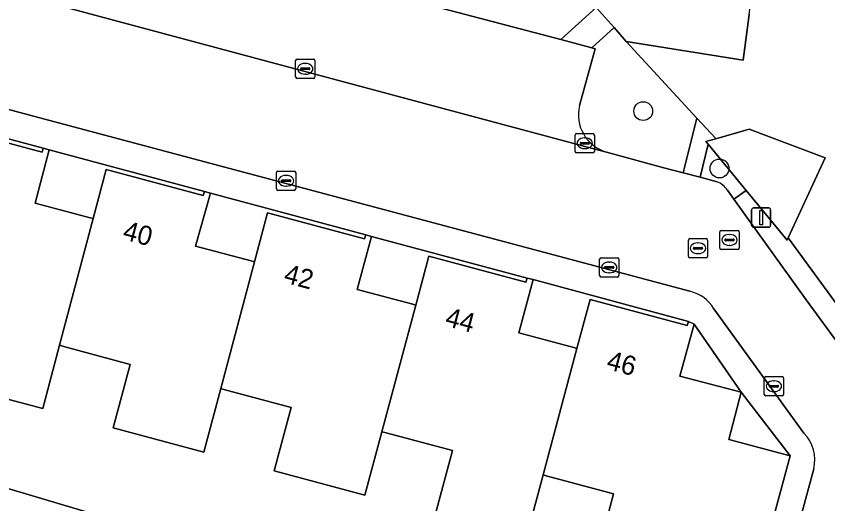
# Model space of a CAD drawing. Extents: x 162989 to 165008, y 383432 to 384338.
# Drawn here: x 163614.99 to 163657.21, y 383922.58 to 383947.94 of the extents above; entities that cross this region are included whole.
import ezdxf

# ---------------------------------------------------------------- set-up
doc = ezdxf.new("R2010")
doc.units = 0
for name, color, linetype in [('IMGEO_Boom', 7, 'Continuous'), ('IMGEO_Erf', 7, 'Continuous'), ('IMGEO_Geluidsscherm', 7, 'Continuous'), ('IMGEO_Grasland_overig', 7, 'Continuous'), ('IMGEO_Groenvoorziening', 7, 'Continuous'), ('IMGEO_Kolk', 7, 'Continuous'), ('IMGEO_Lichtmast', 7, 'Continuous'), ('IMGEO_Pand', 7, 'Continuous'), ('IMGEO_Pand_nummerreeks', 7, 'Continuous'), ('IMGEO_Parkeervlak_open', 7, 'Continuous'), ('IMGEO_Rijbaan_lokaal_open', 7, 'Continuous'), ('IMGEO_Rioolput', 7, 'Continuous'), ('IMGEO_Voetpad_open', 7, 'Continuous')]:
    doc.layers.add(name, color=color, linetype=linetype)

msp = doc.modelspace()

# ---------------------------------------------------------------- linework, layer by layer
at = {"layer": 'IMGEO_Boom'}
for centre in [(163647.609, 383943.003), (163651.576, 383940.019)]:
    msp.add_circle(centre, 0.489, dxfattribs=at)
at = {"layer": 'IMGEO_Erf'}
for points in [[(163653.122, 383948.03), (163652.805, 383945.653), (163646.728, 383946.625), (163650.396, 383942.642), (163651.363, 383941.592), (163651.385, 383941.562), (163653.125, 383942.063), (163657.071, 383940.58), (163655.156, 383936.406), (163662.9, 383925.817)], [(163564.646, 383935.431), (163579.692, 383931.881), (163589.465, 383929.727), (163599.072, 383927.517), (163605.168, 383926.118), (163613.02, 383923.823), (163634.587, 383917.404), (163655.721, 383911.082), (163672.29, 383906.041)], [(163673.981, 383906.039), (163651.937, 383912.722), (163653.247, 383917.636), (163645.188, 383919.799), (163646.071, 383923.092), (163642.556, 383924.039), (163642.4, 383924.081), (163641.519, 383920.786), (163636.802, 383922.049), (163637.684, 383925.343), (163634.164, 383926.279), (163634.006, 383926.321), (163633.124, 383923.028), (163628.41, 383924.295), (163629.295, 383927.588), (163625.786, 383928.523), (163625.624, 383928.567), (163624.746, 383925.272), (163620.03, 383926.538), (163620.914, 383929.831), (163617.398, 383930.782), (163617.242, 383930.824), (163616.366, 383927.527), (163611.629, 383928.789)]]:
    msp.add_lwpolyline(points, dxfattribs=at)
for points in [[(163616.395, 383941.068), (163610.107, 383942.758), (163608.296, 383943.245), (163607.535, 383940.488), (163610.436, 383939.707), (163610.597, 383939.663), (163611.276, 383942.214), (163616.331, 383940.858)], [(163624.788, 383938.825), (163616.704, 383940.986), (163615.972, 383938.221), (163618.835, 383937.451), (163618.992, 383937.409), (163619.67, 383939.96), (163624.72, 383938.612)], [(163633.173, 383936.569), (163625.089, 383938.741), (163624.318, 383935.986), (163627.217, 383935.207), (163627.378, 383935.164), (163628.057, 383937.715), (163633.113, 383936.354)], [(163641.567, 383934.32), (163633.48, 383936.485), (163632.721, 383933.728), (163635.615, 383932.954), (163635.771, 383932.912), (163636.454, 383935.462), (163641.499, 383934.108)], [(163649.958, 383932.065), (163641.878, 383934.236), (163641.13, 383931.476), (163644.006, 383930.701), (163644.16, 383930.659), (163644.843, 383933.211), (163649.9, 383931.859)], [(163650.253, 383931.917), (163649.521, 383929.222), (163652.71, 383928.376)], [(163652.71, 383928.376), (163652.069, 383925.927), (163655.256, 383925.07)]]:
    msp.add_lwpolyline(points, close=True, dxfattribs=at)
at = {"layer": 'IMGEO_Geluidsscherm'}
msp.add_lwpolyline([(163555.79, 383937.222), (163564.646, 383935.431), (163579.692, 383931.881), (163589.465, 383929.727), (163599.072, 383927.517), (163605.168, 383926.118), (163613.02, 383923.823), (163634.587, 383917.404), (163655.721, 383911.082), (163672.29, 383906.041), (163680.003, 383903.652), (163680.457, 383903.531)], dxfattribs=at)
at = {"layer": 'IMGEO_Grasland_overig'}
msp.add_lwpolyline([(163569.036, 383926.529), (163593.547, 383921.194), (163594.114, 383923.205), (163597.332, 383922.493), (163596.824, 383920.182), (163602.361, 383919.022), (163634.665, 383911.508), (163670.387, 383902.701), (163679.08, 383900.453), (163680.003, 383903.652), (163672.29, 383906.041), (163655.721, 383911.082), (163634.587, 383917.404), (163613.02, 383923.823), (163605.168, 383926.118), (163599.072, 383927.517), (163589.465, 383929.727), (163579.692, 383931.881), (163564.646, 383935.431)], dxfattribs=at)
at = {"layer": 'IMGEO_Groenvoorziening'}
for points in [[(163599.35, 383960.383), (163598.199, 383961.094), (163597.764, 383962.949), (163596.978, 383962.778), (163597.581, 383959.99), (163597.843, 383958.853), (163614.246, 383954.444), (163635.514, 383948.776), (163643.317, 383946.719), (163645.161, 383948.398)], [(163650.396, 383942.642), (163646.728, 383946.625), (163646.09, 383947.347), (163644.933, 383946.293), (163645.105, 383946.248), (163644.299, 383943.287)], [(163645.699, 383940.867), (163648.69, 383940.057), (163649.686, 383939.794), (163650.396, 383942.642)], [(163650.987, 383941.275), (163650.575, 383939.559), (163651.448, 383939.329)], [(163651.994, 383938.891), (163652.317, 383938.42), (163652.965, 383938.873), (163650.987, 383941.275)]]:
    msp.add_lwpolyline(points, dxfattribs=at)
for centre, radius, start, end in [((163646.258, 383942.805), 2.017, 166.1857, 253.9141), ((163650.962, 383938.164), 1.262, 35.1609, 67.3661)]:
    msp.add_arc(centre, radius, start, end, dxfattribs=at)
at = {"layer": 'IMGEO_Kolk'}
for p, q in [((163629.525, 383944.776), (163629.525, 383945.628)), ((163629.6, 383945.702), (163630.452, 383945.702)), ((163630.013, 383945.482), (163630.038, 383945.482)), ((163630.526, 383945.628), (163630.526, 383944.776)), ((163629.784, 383945.196), (163629.784, 383945.208)), ((163630.222, 383945.159), (163629.824, 383945.159)), ((163629.827, 383945.245), (163630.225, 383945.245)), ((163630.036, 383944.922), (163630.011, 383944.922)), ((163630.268, 383945.208), (163630.268, 383945.196)), ((163630.452, 383944.702), (163629.6, 383944.702)), ((163644.066, 383940.906), (163644.066, 383941.758)), ((163644.141, 383941.832), (163644.993, 383941.832)), ((163644.554, 383941.612), (163644.579, 383941.612)), ((163645.067, 383941.758), (163645.067, 383940.906)), ((163644.325, 383941.326), (163644.325, 383941.338)), ((163644.763, 383941.289), (163644.365, 383941.289)), ((163644.368, 383941.375), (163644.766, 383941.375)), ((163644.809, 383941.338), (163644.809, 383941.326)), ((163644.993, 383940.832), (163644.141, 383940.832)), ((163644.577, 383941.052), (163644.552, 383941.052)), ((163628.601, 383939.879), (163629.453, 383939.879)), ((163628.526, 383938.953), (163628.526, 383939.805)), ((163628.828, 383939.422), (163629.226, 383939.422)), ((163629.014, 383939.659), (163629.039, 383939.659)), ((163629.527, 383939.805), (163629.527, 383938.953)), ((163628.785, 383939.373), (163628.785, 383939.385)), ((163629.223, 383939.336), (163628.825, 383939.336)), ((163629.037, 383939.099), (163629.012, 383939.099)), ((163629.269, 383939.385), (163629.269, 383939.373)), ((163629.453, 383938.879), (163628.601, 383938.879)), ((163645.339, 383934.447), (163645.339, 383935.299)), ((163645.414, 383935.373), (163646.266, 383935.373)), ((163646.34, 383935.299), (163646.34, 383934.447)), ((163645.598, 383934.867), (163645.598, 383934.879)), ((163646.036, 383934.83), (163645.638, 383934.83)), ((163645.641, 383934.916), (163646.039, 383934.916)), ((163645.827, 383935.153), (163645.852, 383935.153)), ((163646.082, 383934.879), (163646.082, 383934.867)), ((163646.266, 383934.373), (163645.414, 383934.373)), ((163645.85, 383934.593), (163645.825, 383934.593)), ((163653.908, 383928.268), (163653.908, 383929.12)), ((163653.983, 383929.194), (163654.835, 383929.194)), ((163654.396, 383928.974), (163654.421, 383928.974)), ((163654.909, 383929.12), (163654.909, 383928.268)), ((163654.167, 383928.688), (163654.167, 383928.7)), ((163654.605, 383928.651), (163654.207, 383928.651)), ((163654.21, 383928.737), (163654.608, 383928.737)), ((163654.651, 383928.7), (163654.651, 383928.688)), ((163654.835, 383928.194), (163653.983, 383928.194)), ((163654.419, 383928.414), (163654.394, 383928.414))]:
    msp.add_line(p, q, dxfattribs=at)
for points in [[(163629.525, 383944.776), (163629.525, 383945.628)], [(163629.6, 383945.702), (163630.452, 383945.702)], [(163630.526, 383945.628), (163630.526, 383944.776)], [(163630.452, 383944.702), (163629.6, 383944.702)], [(163644.066, 383940.906), (163644.066, 383941.758)], [(163644.141, 383941.832), (163644.993, 383941.832)], [(163645.067, 383941.758), (163645.067, 383940.906)], [(163644.993, 383940.832), (163644.141, 383940.832)], [(163628.601, 383939.879), (163629.453, 383939.879)], [(163628.526, 383938.953), (163628.526, 383939.805)], [(163629.527, 383939.805), (163629.527, 383938.953)], [(163629.453, 383938.879), (163628.601, 383938.879)], [(163645.339, 383934.447), (163645.339, 383935.299)], [(163645.414, 383935.373), (163646.266, 383935.373)], [(163646.34, 383935.299), (163646.34, 383934.447)], [(163646.266, 383934.373), (163645.414, 383934.373)], [(163653.908, 383928.268), (163653.908, 383929.12)], [(163653.983, 383929.194), (163654.835, 383929.194)], [(163654.909, 383929.12), (163654.909, 383928.268)], [(163654.835, 383928.194), (163653.983, 383928.194)]]:
    msp.add_lwpolyline(points, dxfattribs=at)
for centre, radius, start, end in [((163629.602, 383945.626), 0.0765, 91.552, 178.448), ((163629.602, 383945.626), 0.0765, 91.552, 178.448), ((163630.45, 383945.626), 0.0765, 1.552, 88.448), ((163630.45, 383945.626), 0.0765, 1.552, 88.448), ((163629.824, 383945.205), 0.0403, 85.8775, 175.7526), ((163629.821, 383945.195), 0.0366, 178.938, 274.7102), ((163630.225, 383945.202), 0.043, 264.8664, 352.4533), ((163630.229, 383945.207), 0.0386, 1.7309, 96.639), ((163629.602, 383944.778), 0.0765, 181.552, 268.448), ((163629.602, 383944.778), 0.0765, 181.552, 268.448), ((163630.45, 383944.778), 0.0765, 271.552, 358.448), ((163630.45, 383944.778), 0.0765, 271.552, 358.448), ((163644.143, 383941.756), 0.0765, 91.552, 178.448), ((163644.143, 383941.756), 0.0765, 91.552, 178.448), ((163644.991, 383941.756), 0.0765, 1.552, 88.448), ((163644.991, 383941.756), 0.0765, 1.552, 88.448), ((163644.365, 383941.335), 0.0403, 85.8775, 175.7526), ((163644.362, 383941.325), 0.0366, 178.938, 274.7102), ((163644.766, 383941.332), 0.043, 264.8664, 352.4533), ((163644.77, 383941.337), 0.0386, 1.7309, 96.639), ((163644.143, 383940.908), 0.0765, 181.552, 268.448), ((163644.143, 383940.908), 0.0765, 181.552, 268.448), ((163644.991, 383940.908), 0.0765, 271.552, 358.448), ((163644.991, 383940.908), 0.0765, 271.552, 358.448), ((163628.603, 383939.803), 0.0765, 91.552, 178.448), ((163628.603, 383939.803), 0.0765, 91.552, 178.448), ((163629.451, 383939.803), 0.0765, 1.552, 88.448), ((163629.451, 383939.803), 0.0765, 1.552, 88.448), ((163628.825, 383939.382), 0.0403, 85.8775, 175.7526), ((163629.23, 383939.384), 0.0386, 1.7309, 96.639), ((163628.822, 383939.372), 0.0366, 178.938, 274.7102), ((163629.226, 383939.379), 0.043, 264.8664, 352.4533), ((163628.603, 383938.955), 0.0765, 181.552, 268.448), ((163628.603, 383938.955), 0.0765, 181.552, 268.448), ((163629.451, 383938.955), 0.0765, 271.552, 358.448), ((163629.451, 383938.955), 0.0765, 271.552, 358.448), ((163645.416, 383935.297), 0.0765, 91.552, 178.448), ((163645.416, 383935.297), 0.0765, 91.552, 178.448), ((163646.264, 383935.297), 0.0765, 1.552, 88.448), ((163646.264, 383935.297), 0.0765, 1.552, 88.448), ((163645.638, 383934.876), 0.0403, 85.8775, 175.7526), ((163645.635, 383934.866), 0.0366, 178.938, 274.7102), ((163646.039, 383934.873), 0.043, 264.8664, 352.4533), ((163646.043, 383934.878), 0.0386, 1.7309, 96.639), ((163645.416, 383934.449), 0.0765, 181.552, 268.448), ((163645.416, 383934.449), 0.0765, 181.552, 268.448), ((163646.264, 383934.449), 0.0765, 271.552, 358.448), ((163646.264, 383934.449), 0.0765, 271.552, 358.448), ((163653.985, 383929.118), 0.0765, 91.552, 178.448), ((163653.985, 383929.118), 0.0765, 91.552, 178.448), ((163654.833, 383929.118), 0.0765, 1.552, 88.448), ((163654.833, 383929.118), 0.0765, 1.552, 88.448), ((163654.207, 383928.697), 0.0403, 85.8775, 175.7526), ((163654.204, 383928.687), 0.0366, 178.938, 274.7102), ((163654.608, 383928.694), 0.043, 264.8664, 352.4533), ((163654.612, 383928.699), 0.0386, 1.7309, 96.639), ((163653.985, 383928.27), 0.0765, 181.552, 268.448), ((163653.985, 383928.27), 0.0765, 181.552, 268.448), ((163654.833, 383928.27), 0.0765, 271.552, 358.448), ((163654.833, 383928.27), 0.0765, 271.552, 358.448)]:
    msp.add_arc(centre, radius, start, end, dxfattribs=at)
for centre, major_axis, ratio, start_param, end_param in [((163630.012, 383945.202), (-0.387, 0.002), 0.722429, 4.712389, 7.853982), ((163630.037, 383945.202), (-0.39, 0.002), 0.717154, 1.570796, 4.712389), ((163644.553, 383941.332), (-0.387, 0.002), 0.722429, 4.712389, 7.853982), ((163644.578, 383941.332), (-0.39, 0.002), 0.717154, 1.570796, 4.712389), ((163629.013, 383939.379), (-0.387, 0.002), 0.722429, 4.712389, 7.853982), ((163629.038, 383939.379), (-0.39, 0.002), 0.717154, 1.570796, 4.712389), ((163645.826, 383934.873), (-0.387, 0.002), 0.722429, 4.712389, 7.853982), ((163645.851, 383934.873), (-0.39, 0.002), 0.717154, 1.570796, 4.712389), ((163654.395, 383928.694), (-0.387, 0.002), 0.722429, 4.712389, 7.853982), ((163654.42, 383928.694), (-0.39, 0.002), 0.717154, 1.570796, 4.712389)]:
    msp.add_ellipse(centre, major_axis=major_axis, ratio=ratio, start_param=start_param, end_param=end_param, dxfattribs=at)
at = {"layer": 'IMGEO_Lichtmast'}
for p, q in [((163653.248, 383937.064), (163653.248, 383937.864)), ((163653.248, 383937.864), (163653.248, 383937.064)), ((163653.348, 383937.964), (163654.138, 383937.964)), ((163654.138, 383937.964), (163653.348, 383937.964)), ((163654.238, 383937.864), (163654.238, 383937.064)), ((163654.238, 383937.064), (163654.238, 383937.864)), ((163654.138, 383936.964), (163653.348, 383936.964)), ((163653.348, 383936.964), (163654.138, 383936.964))]:
    msp.add_line(p, q, dxfattribs=at)
msp.add_lwpolyline([(163653.668, 383937.839), (163653.818, 383937.839), (163653.818, 383937.089), (163653.668, 383937.089), (163653.668, 383937.839)], dxfattribs=at)
for centre, start, end in [((163653.348, 383937.864), 90, 180), ((163653.348, 383937.864), 90, 180), ((163654.138, 383937.864), 0, 90), ((163654.138, 383937.864), 360, 90), ((163653.348, 383937.064), 180, 270), ((163653.348, 383937.064), 180, 270), ((163654.138, 383937.064), 270, 0), ((163654.138, 383937.064), 270, 0)]:
    msp.add_arc(centre, 0.1, start, end, dxfattribs=at)
at = {"layer": 'IMGEO_Pand'}
for points in [[(163653.415, 383950.229), (163647.205, 383950.244), (163645.85, 383949.02), (163645.161, 383948.398), (163646.09, 383947.347), (163646.728, 383946.625), (163652.805, 383945.653), (163653.122, 383948.03)], [(163618.992, 383937.409), (163618.835, 383937.451), (163615.972, 383938.221), (163616.704, 383940.986), (163616.395, 383941.068), (163616.331, 383940.858), (163611.276, 383942.214), (163610.597, 383939.663), (163608.836, 383933.068), (163608.993, 383933.026), (163612.506, 383932.084), (163611.629, 383928.789), (163616.366, 383927.527), (163617.242, 383930.824)], [(163657.071, 383940.58), (163653.125, 383942.063), (163651.385, 383941.562), (163650.872, 383941.415), (163650.987, 383941.275), (163652.965, 383938.873), (163653.62, 383938.078), (163655.099, 383936.282), (163655.156, 383936.406)], [(163627.378, 383935.164), (163627.217, 383935.207), (163624.318, 383935.986), (163625.089, 383938.741), (163624.788, 383938.825), (163624.72, 383938.612), (163619.67, 383939.96), (163618.992, 383937.409), (163617.242, 383930.824), (163617.398, 383930.782), (163620.914, 383929.831), (163620.03, 383926.538), (163624.746, 383925.272), (163625.624, 383928.567)], [(163635.771, 383932.912), (163635.615, 383932.954), (163632.721, 383933.728), (163633.48, 383936.485), (163633.173, 383936.569), (163633.113, 383936.354), (163628.057, 383937.715), (163627.378, 383935.164), (163625.624, 383928.567), (163625.786, 383928.523), (163629.295, 383927.588), (163628.41, 383924.295), (163633.124, 383923.028), (163634.006, 383926.321)], [(163644.16, 383930.659), (163644.006, 383930.701), (163641.13, 383931.476), (163641.878, 383934.236), (163641.567, 383934.32), (163641.499, 383934.108), (163636.454, 383935.462), (163635.771, 383932.912), (163634.006, 383926.321), (163634.164, 383926.279), (163637.684, 383925.343), (163636.802, 383922.049), (163641.519, 383920.786), (163642.4, 383924.081)], [(163652.71, 383928.376), (163649.521, 383929.222), (163650.253, 383931.917), (163649.958, 383932.065), (163649.9, 383931.859), (163644.843, 383933.211), (163644.16, 383930.659), (163642.4, 383924.081), (163642.556, 383924.039), (163646.071, 383923.092), (163645.188, 383919.799), (163653.247, 383917.636), (163655.256, 383925.07), (163652.069, 383925.927)]]:
    msp.add_lwpolyline(points, close=True, dxfattribs=at)
at = {"layer": 'IMGEO_Parkeervlak_open'}
for points in [[(163644.299, 383943.287), (163645.105, 383946.248), (163644.933, 383946.293), (163643.317, 383946.719), (163635.514, 383948.776), (163614.246, 383954.444), (163597.843, 383958.853)], [(163596.338, 383954.095), (163598.503, 383953.515), (163613.036, 383949.618), (163631.635, 383944.624), (163644.707, 383941.132), (163645.699, 383940.867)]]:
    msp.add_lwpolyline(points, dxfattribs=at)
msp.add_lwpolyline([(163655.156, 383936.406), (163655.099, 383936.282), (163653.62, 383938.078), (163652.965, 383938.873), (163652.317, 383938.42), (163656.091, 383933.18), (163661.213, 383926.178), (163662.881, 383925.747), (163662.9, 383925.817)], close=True, dxfattribs=at)
msp.add_arc((163646.258, 383942.805), 2.017, 166.1857, 253.9141, dxfattribs=at)
at = {"layer": 'IMGEO_Rijbaan_lokaal_open'}
for points in [[(163594.623, 383955.718), (163594.543, 383955.908), (163594.067, 383957.923), (163592.074, 383967.448), (163590.906, 383972.826), (163586.73, 383992.527), (163586.661, 383992.819), (163586.603, 383993.258), (163582.284, 383991.686), (163583.125, 383987.664), (163587.549, 383967.036), (163590.09, 383955.124), (163591.682, 383949.215), (163602.315, 383946.365), (163616.922, 383942.467), (163650.042, 383933.629)], [(163651.448, 383939.329), (163650.575, 383939.559), (163649.686, 383939.794), (163648.69, 383940.057), (163645.699, 383940.867), (163644.707, 383941.132), (163631.635, 383944.624), (163613.036, 383949.618), (163598.503, 383953.515), (163596.338, 383954.095)], [(163656.482, 383924.392), (163654.667, 383917.689), (163673.762, 383912.585), (163675.48, 383912.126), (163675.505, 383912.228), (163676.076, 383914.207), (163676.895, 383917.244), (163677.637, 383919.996), (163678.094, 383921.638), (163672.545, 383923.205), (163669.055, 383924.191), (163662.9, 383925.817), (163662.881, 383925.747), (163661.213, 383926.178), (163656.091, 383933.18), (163652.317, 383938.42), (163651.994, 383938.891)], [(163651.279, 383932.718), (163655.97, 383926.257)]]:
    msp.add_lwpolyline(points, dxfattribs=at)
for centre, radius, start, end in [((163650.962, 383938.164), 1.262, 35.1609, 67.3661), ((163649.626, 383931.769), 1.906, 29.8582, 77.4016), ((163654.551, 383924.865), 1.988, 346.2419, 44.4606)]:
    msp.add_arc(centre, radius, start, end, dxfattribs=at)
at = {"layer": 'IMGEO_Rioolput'}
for p, q in [((163651.597, 383935.874), (163651.597, 383936.726)), ((163651.672, 383936.8), (163652.524, 383936.8)), ((163652.085, 383936.58), (163652.11, 383936.58)), ((163652.598, 383936.726), (163652.598, 383935.874)), ((163649.958, 383935.442), (163649.958, 383936.294)), ((163650.033, 383936.368), (163650.885, 383936.368)), ((163650.446, 383936.148), (163650.471, 383936.148)), ((163650.959, 383936.294), (163650.959, 383935.442)), ((163651.856, 383936.294), (163651.856, 383936.306)), ((163652.294, 383936.257), (163651.896, 383936.257)), ((163651.899, 383936.343), (163652.297, 383936.343)), ((163652.34, 383936.306), (163652.34, 383936.294)), ((163650.217, 383935.862), (163650.217, 383935.874)), ((163650.655, 383935.825), (163650.257, 383935.825)), ((163650.26, 383935.911), (163650.658, 383935.911)), ((163650.701, 383935.874), (163650.701, 383935.862)), ((163652.524, 383935.8), (163651.672, 383935.8)), ((163652.108, 383936.02), (163652.083, 383936.02)), ((163650.885, 383935.368), (163650.033, 383935.368)), ((163650.469, 383935.588), (163650.444, 383935.588))]:
    msp.add_line(p, q, dxfattribs=at)
for points in [[(163651.597, 383935.874), (163651.597, 383936.726)], [(163651.672, 383936.8), (163652.524, 383936.8)], [(163652.598, 383936.726), (163652.598, 383935.874)], [(163649.958, 383935.442), (163649.958, 383936.294)], [(163650.033, 383936.368), (163650.885, 383936.368)], [(163650.959, 383936.294), (163650.959, 383935.442)], [(163652.524, 383935.8), (163651.672, 383935.8)], [(163650.885, 383935.368), (163650.033, 383935.368)]]:
    msp.add_lwpolyline(points, dxfattribs=at)
for centre, radius, start, end in [((163651.674, 383936.724), 0.0765, 91.552, 178.448), ((163651.674, 383936.724), 0.0765, 91.552, 178.448), ((163652.522, 383936.724), 0.0765, 1.552, 88.448), ((163652.522, 383936.724), 0.0765, 1.552, 88.448), ((163650.035, 383936.292), 0.0765, 91.552, 178.448), ((163650.035, 383936.292), 0.0765, 91.552, 178.448), ((163650.883, 383936.292), 0.0765, 1.552, 88.448), ((163650.883, 383936.292), 0.0765, 1.552, 88.448), ((163651.896, 383936.303), 0.0403, 85.8775, 175.7526), ((163651.893, 383936.293), 0.0366, 178.938, 274.7102), ((163652.297, 383936.3), 0.043, 264.8664, 352.4533), ((163652.301, 383936.305), 0.0386, 1.7309, 96.639), ((163650.257, 383935.871), 0.0403, 85.8775, 175.7526), ((163650.254, 383935.861), 0.0366, 178.938, 274.7102), ((163650.658, 383935.868), 0.043, 264.8664, 352.4533), ((163650.662, 383935.873), 0.0386, 1.7309, 96.639), ((163651.674, 383935.876), 0.0765, 181.552, 268.448), ((163651.674, 383935.876), 0.0765, 181.552, 268.448), ((163652.522, 383935.876), 0.0765, 271.552, 358.448), ((163652.522, 383935.876), 0.0765, 271.552, 358.448), ((163650.035, 383935.444), 0.0765, 181.552, 268.448), ((163650.035, 383935.444), 0.0765, 181.552, 268.448), ((163650.883, 383935.444), 0.0765, 271.552, 358.448), ((163650.883, 383935.444), 0.0765, 271.552, 358.448)]:
    msp.add_arc(centre, radius, start, end, dxfattribs=at)
for centre, major_axis, ratio, start_param, end_param in [((163652.084, 383936.3), (-0.387, 0.002), 0.722429, 4.712389, 7.853982), ((163652.109, 383936.3), (-0.39, 0.002), 0.717154, 1.570796, 4.712389), ((163650.445, 383935.868), (-0.387, 0.002), 0.722429, 4.712389, 7.853982), ((163650.47, 383935.868), (-0.39, 0.002), 0.717154, 1.570796, 4.712389)]:
    msp.add_ellipse(centre, major_axis=major_axis, ratio=ratio, start_param=start_param, end_param=end_param, dxfattribs=at)
at = {"layer": 'IMGEO_Voetpad_open'}
for points in [[(163583.125, 383949.978), (163591.199, 383947.82), (163591.513, 383947.737), (163599.6, 383945.572), (163599.908, 383945.487), (163607.992, 383943.329), (163608.296, 383943.245), (163610.107, 383942.758), (163616.395, 383941.068), (163616.704, 383940.986), (163624.788, 383938.825), (163625.089, 383938.741), (163633.173, 383936.569), (163633.48, 383936.485), (163641.567, 383934.32), (163641.878, 383934.236), (163649.958, 383932.065), (163650.253, 383931.917), (163652.71, 383928.376), (163655.256, 383925.07), (163653.247, 383917.636), (163651.937, 383912.722), (163673.981, 383906.039)], [(163650.042, 383933.629), (163616.922, 383942.467), (163602.315, 383946.365), (163591.682, 383949.215)], [(163655.97, 383926.257), (163651.279, 383932.718)], [(163658.354, 383911.519), (163653.533, 383913.106), (163654.667, 383917.689), (163656.482, 383924.392)]]:
    msp.add_lwpolyline(points, dxfattribs=at)
for points in [[(163646.09, 383947.347), (163645.161, 383948.398), (163643.317, 383946.719), (163644.933, 383946.293)], [(163650.987, 383941.275), (163650.872, 383941.415), (163651.385, 383941.562), (163651.363, 383941.592), (163650.396, 383942.642), (163649.686, 383939.794), (163650.575, 383939.559)]]:
    msp.add_lwpolyline(points, close=True, dxfattribs=at)
for centre, radius, start, end in [((163649.626, 383931.769), 1.906, 29.8582, 77.4016), ((163654.551, 383924.865), 1.988, 346.2419, 44.4606)]:
    msp.add_arc(centre, radius, start, end, dxfattribs=at)

# ---------------------------------------------------------------- texts
at = {"layer": 'IMGEO_Pand_nummerreeks'}
for s, rotation, p in [('40', 345.0573, (163620.477, 383936.35)), ('42', 344.9369, (163628.854, 383934.104)), ('44', 344.9828, (163637.252, 383931.852)), ('46', 345.0343, (163645.649, 383929.6))]:
    msp.add_text(s, height=1, rotation=rotation, dxfattribs=at).set_placement(p)

doc.saveas('drawing.dxf')
